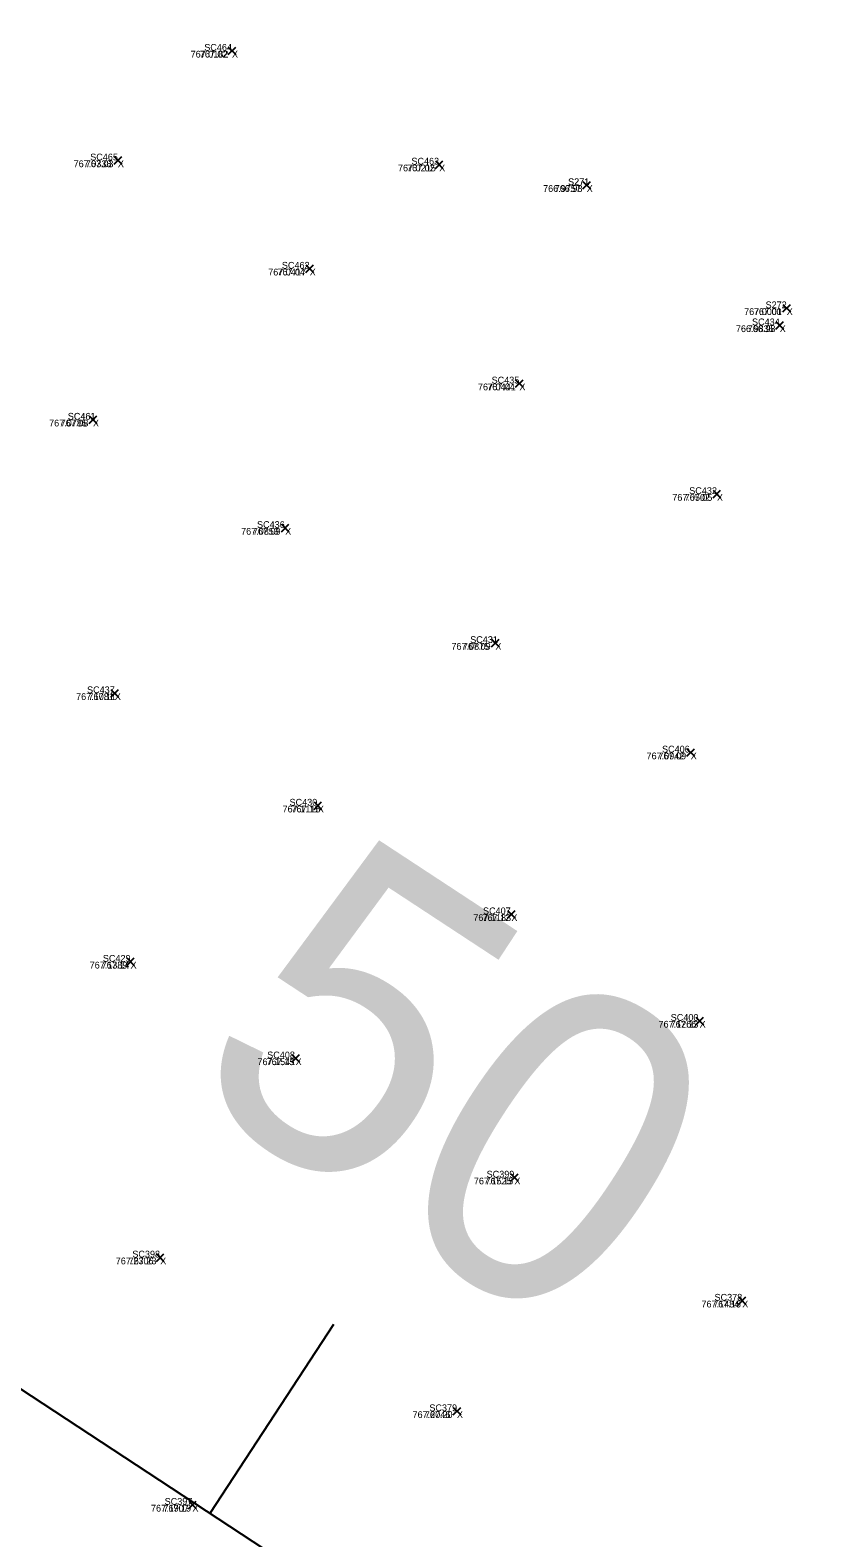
# Model space of a CAD drawing. Extents: x 1845019 to 1877956, y 680444 to 701081.
# Drawn here: x 1857646.92 to 1857653.94, y 694289.61 to 694302.95 of the extents above; entities that cross this region are included whole.
import ezdxf

# ---------------------------------------------------------------- set-up
doc = ezdxf.new("R2010")
doc.units = 0
for name, color, linetype in [('SV_X_CL_Survey_20', 7, 'Continuous'), ('SV_X_Random_Point', 7, 'Continuous'), ('SV_X_Text_Comment', 7, 'Continuous'), ('SV_X_Text_Elevation', 7, 'Continuous'), ('SV_X_Text_Name', 7, 'Continuous')]:
    doc.layers.add(name, color=color, linetype=linetype)

msp = doc.modelspace()

# ---------------------------------------------------------------- linework, layer by layer
at = {"layer": 'SV_X_CL_Survey_20'}
for p, q in [((1856038.267, 695346.314), (1858797.327, 693536.085)), ((1857648.511, 694289.827), (1857649.608, 694291.499))]:
    msp.add_line(p, q, dxfattribs=at)
at = {"layer": 'SV_X_Random_Point'}
for p, q in [((1857648.672, 694302.733), (1857648.738, 694302.8)), ((1857648.672, 694302.8), (1857648.738, 694302.733)), ((1857648.672, 694302.733), (1857648.738, 694302.8)), ((1857648.672, 694302.8), (1857648.738, 694302.733)), ((1857647.662, 694301.764), (1857647.729, 694301.831)), ((1857647.662, 694301.831), (1857647.729, 694301.764)), ((1857647.662, 694301.764), (1857647.729, 694301.831)), ((1857647.662, 694301.831), (1857647.729, 694301.764)), ((1857650.507, 694301.726), (1857650.573, 694301.793)), ((1857650.507, 694301.793), (1857650.573, 694301.726)), ((1857650.507, 694301.726), (1857650.573, 694301.793)), ((1857650.507, 694301.793), (1857650.573, 694301.726)), ((1857651.813, 694301.544), (1857651.88, 694301.611)), ((1857651.813, 694301.611), (1857651.88, 694301.544)), ((1857651.813, 694301.544), (1857651.88, 694301.611)), ((1857651.813, 694301.611), (1857651.88, 694301.544)), ((1857649.359, 694300.806), (1857649.426, 694300.872)), ((1857649.359, 694300.872), (1857649.426, 694300.806)), ((1857649.359, 694300.806), (1857649.426, 694300.872)), ((1857649.359, 694300.872), (1857649.426, 694300.806)), ((1857653.584, 694300.456), (1857653.651, 694300.523)), ((1857653.584, 694300.523), (1857653.651, 694300.456)), ((1857653.584, 694300.456), (1857653.651, 694300.523)), ((1857653.584, 694300.523), (1857653.651, 694300.456)), ((1857653.522, 694300.304), (1857653.588, 694300.371)), ((1857653.522, 694300.371), (1857653.588, 694300.304)), ((1857653.522, 694300.304), (1857653.588, 694300.371)), ((1857653.522, 694300.371), (1857653.588, 694300.304)), ((1857651.217, 694299.79), (1857651.283, 694299.856)), ((1857651.217, 694299.856), (1857651.283, 694299.79)), ((1857651.217, 694299.79), (1857651.283, 694299.856)), ((1857651.217, 694299.856), (1857651.283, 694299.79)), ((1857647.441, 694299.469), (1857647.508, 694299.536)), ((1857647.441, 694299.536), (1857647.508, 694299.469)), ((1857647.441, 694299.469), (1857647.508, 694299.536)), ((1857647.441, 694299.536), (1857647.508, 694299.469)), ((1857652.966, 694298.812), (1857653.032, 694298.879)), ((1857652.966, 694298.879), (1857653.032, 694298.812)), ((1857652.966, 694298.812), (1857653.032, 694298.879)), ((1857652.966, 694298.879), (1857653.032, 694298.812)), ((1857649.143, 694298.512), (1857649.21, 694298.579)), ((1857649.143, 694298.579), (1857649.21, 694298.512)), ((1857649.143, 694298.512), (1857649.21, 694298.579)), ((1857649.143, 694298.579), (1857649.21, 694298.512)), ((1857651.003, 694297.494), (1857651.07, 694297.56)), ((1857651.003, 694297.56), (1857651.07, 694297.494)), ((1857651.003, 694297.494), (1857651.07, 694297.56)), ((1857651.003, 694297.56), (1857651.07, 694297.494)), ((1857647.634, 694297.049), (1857647.701, 694297.116)), ((1857647.634, 694297.116), (1857647.701, 694297.049)), ((1857647.634, 694297.049), (1857647.701, 694297.116)), ((1857647.634, 694297.116), (1857647.701, 694297.049)), ((1857652.733, 694296.525), (1857652.8, 694296.592)), ((1857652.733, 694296.592), (1857652.8, 694296.525)), ((1857652.733, 694296.525), (1857652.8, 694296.592)), ((1857652.733, 694296.592), (1857652.8, 694296.525)), ((1857649.433, 694296.054), (1857649.499, 694296.121)), ((1857649.433, 694296.121), (1857649.499, 694296.054)), ((1857649.433, 694296.054), (1857649.499, 694296.121)), ((1857649.433, 694296.121), (1857649.499, 694296.054)), ((1857651.145, 694295.093), (1857651.212, 694295.16)), ((1857651.145, 694295.16), (1857651.212, 694295.093)), ((1857651.145, 694295.093), (1857651.212, 694295.16)), ((1857651.145, 694295.16), (1857651.212, 694295.093)), ((1857647.773, 694294.674), (1857647.84, 694294.74)), ((1857647.773, 694294.74), (1857647.84, 694294.674)), ((1857647.773, 694294.674), (1857647.84, 694294.74)), ((1857647.773, 694294.74), (1857647.84, 694294.674)), ((1857652.813, 694294.15), (1857652.879, 694294.217)), ((1857652.813, 694294.217), (1857652.879, 694294.15)), ((1857652.813, 694294.15), (1857652.879, 694294.217)), ((1857652.813, 694294.217), (1857652.879, 694294.15)), ((1857649.235, 694293.818), (1857649.302, 694293.885)), ((1857649.235, 694293.885), (1857649.302, 694293.818)), ((1857649.235, 694293.818), (1857649.302, 694293.885)), ((1857649.235, 694293.885), (1857649.302, 694293.818)), ((1857651.173, 694292.764), (1857651.24, 694292.83)), ((1857651.173, 694292.83), (1857651.24, 694292.764)), ((1857651.173, 694292.764), (1857651.24, 694292.83)), ((1857651.173, 694292.83), (1857651.24, 694292.764)), ((1857648.036, 694292.056), (1857648.103, 694292.123)), ((1857648.036, 694292.123), (1857648.103, 694292.056)), ((1857648.036, 694292.056), (1857648.103, 694292.123)), ((1857648.036, 694292.123), (1857648.103, 694292.056)), ((1857653.189, 694291.675), (1857653.256, 694291.742)), ((1857653.189, 694291.742), (1857653.256, 694291.675)), ((1857653.189, 694291.675), (1857653.256, 694291.742)), ((1857653.189, 694291.742), (1857653.256, 694291.675)), ((1857650.664, 694290.697), (1857650.731, 694290.763)), ((1857650.664, 694290.763), (1857650.731, 694290.697)), ((1857650.664, 694290.697), (1857650.731, 694290.763)), ((1857650.664, 694290.763), (1857650.731, 694290.697)), ((1857648.322, 694289.868), (1857648.388, 694289.935)), ((1857648.322, 694289.935), (1857648.388, 694289.868)), ((1857648.322, 694289.868), (1857648.388, 694289.935)), ((1857648.322, 694289.935), (1857648.388, 694289.868))]:
    msp.add_line(p, q, dxfattribs=at)

# ---------------------------------------------------------------- texts
at = {"layer": 'SV_X_CL_Survey_20'}
msp.add_text('50', height=2.8, rotation=326.731, dxfattribs=at).set_placement((1857648.212, 694293.611))
at = {"layer": 'SV_X_Text_Comment'}
for p in [(1857648.705, 694302.707), (1857647.695, 694301.737), (1857650.54, 694301.7), (1857651.846, 694301.518), (1857649.393, 694300.779), (1857653.617, 694300.429), (1857653.555, 694300.278), (1857651.25, 694299.763), (1857647.474, 694299.443), (1857652.999, 694298.785), (1857649.176, 694298.485), (1857651.037, 694297.467), (1857647.668, 694297.023), (1857652.767, 694296.498), (1857649.466, 694296.028), (1857651.179, 694295.067), (1857647.807, 694294.647), (1857652.846, 694294.124), (1857649.268, 694293.792), (1857651.206, 694292.737), (1857648.07, 694292.03), (1857653.223, 694291.648), (1857650.697, 694290.67), (1857648.355, 694289.842)]:
    msp.add_text('X', height=0.06, dxfattribs=at).set_placement(p)
at = {"layer": 'SV_X_Text_Elevation'}
for s, p in [('767.0182', (1857648.339, 694302.707)), ('767.02', (1857648.42, 694302.707)), ('767.0338', (1857647.303, 694301.737)), ('767.03', (1857647.41, 694301.737)), ('767.0215', (1857650.175, 694301.7)), ('767.02', (1857650.255, 694301.7)), ('766.9757', (1857651.46, 694301.518)), ('766.98', (1857651.563, 694301.518)), ('767.0417', (1857649.026, 694300.779)), ('767.04', (1857649.107, 694300.779)), ('767.0001', (1857653.24, 694300.429)), ('767.00', (1857653.326, 694300.429)), ('766.9835', (1857653.167, 694300.278)), ('766.98', (1857653.272, 694300.278)), ('767.0441', (1857650.883, 694299.763)), ('767.04', (1857650.965, 694299.763)), ('767.0785', (1857647.086, 694299.443)), ('767.08', (1857647.188, 694299.443)), ('767.0502', (1857652.604, 694298.785)), ('767.05', (1857652.713, 694298.785)), ('767.0859', (1857648.786, 694298.485)), ('767.09', (1857648.89, 694298.485)), ('767.0875', (1857650.648, 694297.467)), ('767.09', (1857650.75, 694297.467)), ('767.1081', (1857647.325, 694297.023)), ('767.11', (1857647.434, 694297.023)), ('767.0942', (1857652.376, 694296.498)), ('767.09', (1857652.481, 694296.498)), ('767.1115', (1857649.153, 694296.028)), ('767.11', (1857649.232, 694296.028)), ('767.1183', (1857650.842, 694295.067)), ('767.12', (1857650.923, 694295.067)), ('767.1389', (1857647.445, 694294.647)), ('767.14', (1857647.551, 694294.647)), ('767.1266', (1857652.482, 694294.124)), ('767.13', (1857652.589, 694294.124)), ('767.1541', (1857648.931, 694293.792)), ('767.15', (1857649.012, 694293.792)), ('767.1525', (1857650.847, 694292.737)), ('767.15', (1857650.95, 694292.737)), ('767.2306', (1857647.676, 694292.03)), ('767.23', (1857647.791, 694292.03)), ('767.1484', (1857652.862, 694291.648)), ('767.15', (1857652.966, 694291.648)), ('767.2046', (1857650.304, 694290.67)), ('767.20', (1857650.413, 694290.67)), ('767.1907', (1857647.988, 694289.842)), ('767.19', (1857648.098, 694289.842))]:
    msp.add_text(s, height=0.06, dxfattribs=at).set_placement(p)
at = {"layer": 'SV_X_Text_Name'}
for s, p in [('SC464', (1857648.46, 694302.767)), ('SC464', (1857648.46, 694302.767)), ('SC465', (1857647.45, 694301.797)), ('SC465', (1857647.45, 694301.797)), ('SC463', (1857650.294, 694301.76)), ('SC463', (1857650.294, 694301.76)), ('S271', (1857651.681, 694301.578)), ('S271', (1857651.682, 694301.578)), ('SC462', (1857649.147, 694300.839)), ('SC462', (1857649.147, 694300.839)), ('S272', (1857653.43, 694300.489)), ('S272', (1857653.43, 694300.489)), ('SC434', (1857653.31, 694300.338)), ('SC434', (1857653.31, 694300.338)), ('SC435', (1857651.004, 694299.823)), ('SC435', (1857651.004, 694299.823)), ('SC461', (1857647.251, 694299.503)), ('SC461', (1857647.252, 694299.503)), ('SC432', (1857652.754, 694298.845)), ('SC432', (1857652.754, 694298.845)), ('SC436', (1857648.927, 694298.545)), ('SC436', (1857648.927, 694298.545)), ('SC431', (1857650.814, 694297.527)), ('SC431', (1857650.815, 694297.527)), ('SC437', (1857647.422, 694297.083)), ('SC437', (1857647.422, 694297.083)), ('SC406', (1857652.513, 694296.558)), ('SC406', (1857652.513, 694296.558)), ('SC430', (1857649.215, 694296.088)), ('SC430', (1857649.215, 694296.088)), ('SC407', (1857650.928, 694295.127)), ('SC407', (1857650.928, 694295.127)), ('SC429', (1857647.562, 694294.707)), ('SC429', (1857647.562, 694294.707)), ('SC400', (1857652.59, 694294.184)), ('SC400', (1857652.59, 694294.184)), ('SC408', (1857649.017, 694293.852)), ('SC408', (1857649.017, 694293.852)), ('SC399', (1857650.96, 694292.797)), ('SC399', (1857650.96, 694292.797)), ('SC398', (1857647.823, 694292.09)), ('SC398', (1857647.823, 694292.09)), ('SC378', (1857652.978, 694291.708)), ('SC378', (1857652.978, 694291.708)), ('SC379', (1857650.453, 694290.73)), ('SC379', (1857650.453, 694290.73)), ('SC397', (1857648.109, 694289.902)), ('SC397', (1857648.109, 694289.902))]:
    msp.add_text(s, height=0.06, dxfattribs=at).set_placement(p)

doc.saveas('drawing.dxf')
